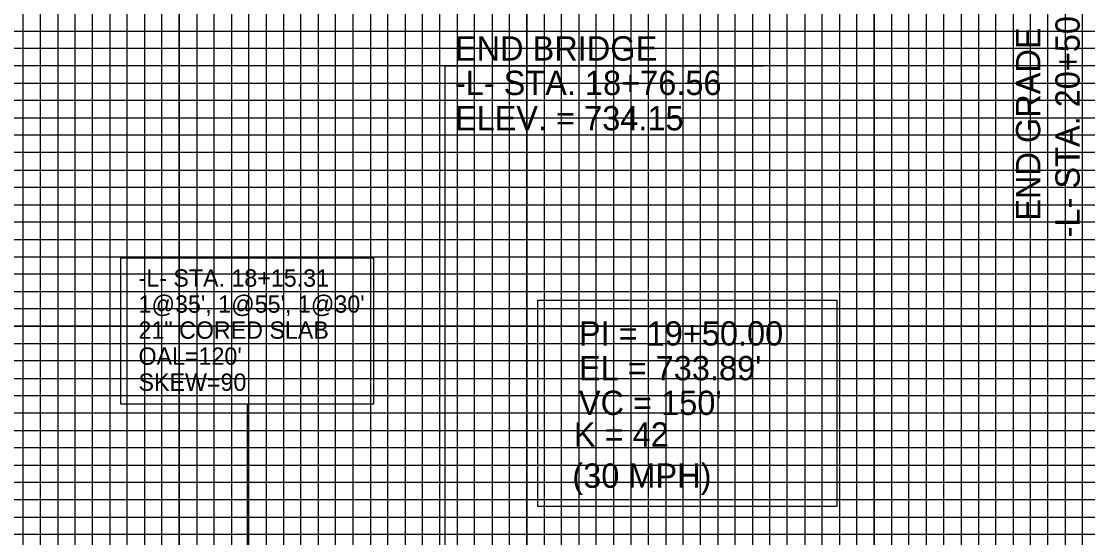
# Model space of a CAD drawing. Extents: x 573926 to 575610, y -51565 to -50465.
# Drawn here: x 574797.3 to 575104.2, y -50800.8 to -50652.1 of the extents above; entities that cross this region are included whole.
import ezdxf

# ---------------------------------------------------------------- set-up
doc = ezdxf.new("R2010")
doc.units = 0
for name, color, linetype in [('Prop Dimension', 7, 'Continuous'), ('Prop Dimension Text', 7, 'Continuous'), ('Prop Grid Mask', 7, 'Continuous'), ('Prop Vertical Profile Curve Label', 7, 'Continuous'), ('Prop VPI Label', 7, 'Continuous'), ('Sheet DOT Grid CELL', 7, 'Continuous'), ('Sheet Profile Grid Major CELL', 7, 'Continuous'), ('Sheet Profile Grid Middle CELL', 7, 'Continuous'), ('Sheet Profile Grid Minor CELL', 7, 'Continuous')]:
    doc.layers.add(name, color=color, linetype=linetype)

msp = doc.modelspace()

# ---------------------------------------------------------------- linework, layer by layer
at = {"layer": 'Prop Dimension'}
for p, q in [((575092.78, -50804.5), (575092.78, -50624.54)), ((574919.34, -50819.11), (574919.34, -50664.95)), ((574919.34, -50664.95), (575010.93, -50664.95)), ((574862.33, -50762.43), (574862.33, -50823.86))]:
    msp.add_line(p, q, dxfattribs=at)
at = {"layer": 'Prop Grid Mask'}
for points in [[(574825.97, -50720.21), (574898.68, -50720.21), (574898.68, -50762.43), (574825.97, -50762.43)], [(574945.95, -50732.44), (575032, -50732.44), (575032, -50791.83), (574945.95, -50791.83)]]:
    msp.add_lwpolyline(points, close=True, dxfattribs=at)
at = {"layer": 'Sheet DOT Grid CELL'}
for p, q in [((574842.78, -50989.95), (574842.78, -50489.95)), ((574892.78, -50989.95), (574892.78, -50489.95)), ((574942.78, -50989.95), (574942.78, -50489.95)), ((574992.78, -50989.95), (574992.78, -50489.95)), ((575042.78, -50989.95), (575042.78, -50489.95)), ((575092.78, -50989.95), (575092.78, -50489.95)), ((575592.78, -50689.95), (574092.78, -50689.95)), ((575592.78, -50739.95), (574092.78, -50739.95)), ((575592.78, -50789.95), (574092.78, -50789.95))]:
    msp.add_line(p, q, dxfattribs=at)
at = {"layer": 'Sheet Profile Grid Major CELL'}
for points in [[(574542.78, -50989.95), (574592.78, -50989.95), (574592.78, -50489.95), (574642.78, -50489.95), (574642.78, -50989.95), (574692.78, -50989.95), (574692.78, -50489.95), (574742.78, -50489.95), (574742.78, -50989.95), (574792.78, -50989.95), (574792.78, -50489.95), (574842.78, -50489.95), (574842.78, -50989.95), (574892.78, -50989.95), (574892.78, -50489.95), (574942.78, -50489.95), (574942.78, -50989.95), (574992.78, -50989.95), (574992.78, -50489.95), (575042.78, -50489.95), (575042.78, -50989.95), (575092.78, -50989.95), (575092.78, -50489.95), (575142.78, -50489.95)], [(575592.78, -50689.95), (574092.78, -50689.95), (574092.78, -50739.95), (575592.78, -50739.95)], [(575592.78, -50789.95), (574092.78, -50789.95), (574092.78, -50839.95), (575592.78, -50839.95)]]:
    msp.add_lwpolyline(points, dxfattribs=at)
at = {"layer": 'Sheet Profile Grid Middle CELL'}
for points in [[(574767.78, -50989.95), (574817.78, -50989.95), (574817.78, -50489.95), (574867.78, -50489.95), (574867.78, -50989.95), (574917.78, -50989.95), (574917.78, -50489.95), (574967.78, -50489.95), (574967.78, -50989.95), (575017.78, -50989.95), (575017.78, -50489.95), (575067.78, -50489.95), (575067.78, -50989.95), (575117.78, -50989.95)], [(575592.78, -50664.95), (574092.78, -50664.95), (574092.78, -50714.95), (575417.78, -50714.95)], [(575592.78, -50764.95), (574092.78, -50764.95), (574092.78, -50814.95), (575592.78, -50814.95)]]:
    msp.add_lwpolyline(points, dxfattribs=at)
at = {"layer": 'Sheet Profile Grid Minor CELL'}
for p, q in [((574142.78, -50654.95), (575542.78, -50654.95)), ((575542.78, -50674.95), (574142.78, -50674.95)), ((574142.78, -50679.95), (575542.78, -50679.95)), ((575542.78, -50699.95), (574142.78, -50699.95)), ((574142.78, -50704.95), (575542.78, -50704.95)), ((575542.78, -50724.95), (574142.78, -50724.95)), ((574142.78, -50729.95), (575542.78, -50729.95)), ((575542.78, -50734.95), (574142.78, -50734.95)), ((574142.78, -50744.95), (575542.78, -50744.95)), ((575542.78, -50749.95), (574142.78, -50749.95)), ((574142.78, -50754.95), (575542.78, -50754.95)), ((575542.78, -50759.95), (574142.78, -50759.95)), ((574142.78, -50769.95), (575542.78, -50769.95)), ((575542.78, -50774.95), (574142.78, -50774.95)), ((574142.78, -50779.95), (575542.78, -50779.95)), ((575542.78, -50784.95), (574142.78, -50784.95)), ((574142.78, -50794.95), (575542.78, -50794.95)), ((575542.78, -50799.95), (574142.78, -50799.95))]:
    msp.add_line(p, q, dxfattribs=at)
for points in [[(574797.78, -50489.95), (574797.78, -50989.95), (574797.78, -50989.95), (574802.78, -50989.95), (574802.78, -50489.95)], [(574807.78, -50489.95), (574807.78, -50989.95), (574812.78, -50989.95), (574812.78, -50489.95)], [(574822.78, -50489.95), (574822.78, -50989.95), (574827.78, -50989.95), (574827.78, -50489.95)], [(574832.78, -50489.95), (574832.78, -50989.95), (574837.78, -50989.95), (574837.78, -50489.95)], [(574847.78, -50489.95), (574847.78, -50989.95), (574852.78, -50989.95), (574852.78, -50489.95)], [(574857.78, -50489.95), (574857.78, -50989.95), (574862.78, -50989.95), (574862.78, -50489.95)], [(574872.78, -50489.95), (574872.78, -50989.95), (574877.78, -50989.95), (574877.78, -50489.95)], [(574882.78, -50489.95), (574882.78, -50989.95), (574887.78, -50989.95), (574887.78, -50489.95)], [(574897.78, -50489.95), (574897.78, -50989.95), (574902.78, -50989.95), (574902.78, -50489.95)], [(574907.78, -50489.95), (574907.78, -50989.95), (574912.78, -50989.95), (574912.78, -50489.95)], [(574922.78, -50489.95), (574922.78, -50989.95), (574927.78, -50989.95), (574927.78, -50489.95)], [(574932.78, -50489.95), (574932.78, -50989.95), (574937.78, -50989.95), (574937.78, -50489.95)], [(574947.78, -50489.95), (574947.78, -50989.95), (574952.48, -50989.4), (574952.78, -50989.95), (574952.78, -50489.95)], [(574957.78, -50489.95), (574957.78, -50989.95), (574962.78, -50989.95), (574962.78, -50489.95)], [(574972.78, -50489.95), (574972.78, -50989.95), (574977.78, -50989.95)], [(574977.78, -50989.95), (574977.78, -50489.95)], [(574982.78, -50489.95), (574982.78, -50989.95), (574987.78, -50989.95), (574987.78, -50489.95)], [(574997.78, -50489.95), (574997.78, -50989.95), (575002.78, -50989.95), (575002.78, -50489.95)], [(575007.78, -50489.95), (575007.78, -50989.95), (575012.78, -50989.95), (575012.78, -50489.95)], [(575022.78, -50489.95), (575022.78, -50989.95), (575027.78, -50989.95), (575027.78, -50489.95)], [(575032.78, -50489.95), (575032.78, -50989.95), (575037.78, -50989.95), (575037.78, -50489.95)], [(575047.78, -50489.95), (575047.78, -50989.95), (575052.78, -50989.95), (575052.78, -50489.95)], [(575057.78, -50489.95), (575057.78, -50989.95), (575062.78, -50989.95), (575062.78, -50489.95)], [(575072.78, -50489.95), (575072.78, -50989.95), (575077.78, -50989.95), (575077.78, -50489.95)], [(575082.78, -50489.95), (575082.78, -50989.95), (575087.78, -50989.95), (575087.78, -50489.95)], [(575097.78, -50489.95), (575097.78, -50989.95), (575102.78, -50989.95), (575102.78, -50489.95)], [(575542.78, -50659.95), (574142.78, -50659.95), (574142.78, -50669.95), (575542.78, -50669.95)], [(575542.78, -50684.95), (574142.78, -50684.95), (574142.78, -50694.95), (575542.78, -50694.95)], [(575542.78, -50709.95), (574142.78, -50709.95), (574142.78, -50719.95), (575542.78, -50719.95)]]:
    msp.add_lwpolyline(points, dxfattribs=at)

# ---------------------------------------------------------------- texts
at = {"layer": 'Prop Dimension Text'}
for s, height, rotation, p in [('-L- STA. 20+50.00', 7, 90, (575101.93, -50714.34)), ('END GRADE', 7, 90, (575090.59, -50709.54)), ('-L- STA. 18+15.31', 5, 0, (574831.04, -50728.55)), ("1@35', 1@55', 1@30'", 5, 0, (574831.04, -50736.05)), ('21" CORED SLAB', 5, 0, (574831.04, -50743.55)), ("OAL=120'", 5, 0, (574831.04, -50751.05)), ('SKEW=90', 5, 0, (574831.04, -50758.55))]:
    msp.add_text(s, height=height, rotation=rotation, dxfattribs=at).set_placement(p)
for s, p in [('END BRIDGE', (574922.09, -50663.43)), ('-L- STA. 18+76.56', (574922.09, -50673.35)), ('ELEV. = 734.15', (574922.09, -50683.53))]:
    msp.add_text(s, height=7, dxfattribs=at).set_placement(p)
at = {"layer": 'Prop Vertical Profile Curve Label'}
for s, p in [("VC = 150'", (574957.78, -50765.5)), ('K = 42', (574956.35, -50774.61)), ('(30 MPH)', (574955.9, -50786.47))]:
    msp.add_text(s, height=7, dxfattribs=at).set_placement(p)
at = {"layer": 'Prop VPI Label'}
for s, p in [('PI = 19+50.00', (574957.78, -50745.5)), ("EL = 733.89'", (574957.78, -50755.5))]:
    msp.add_text(s, height=7, dxfattribs=at).set_placement(p)

doc.saveas('drawing.dxf')
